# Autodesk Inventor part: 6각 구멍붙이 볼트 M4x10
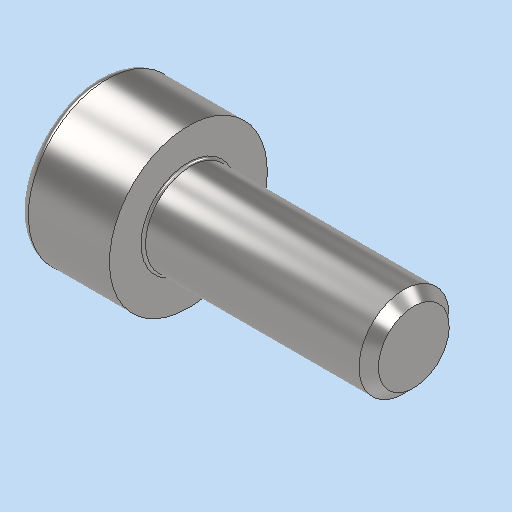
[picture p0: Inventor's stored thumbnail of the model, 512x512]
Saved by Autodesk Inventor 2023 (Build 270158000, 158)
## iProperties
Created: 2026-04
Part Number: 6각 구멍붙이 볼트 M4x10
Material: 강철, 연강
Description: 6각머리 태핑 나사
Document SubType Name: Modeling
Designer: home
Density: 7.85 g/cm^3
Appearance: 기본값
Author: jhkim
Sending System: Autodesk Inventor 2027
Preprocessor: ST-DEVELOPER v20.1
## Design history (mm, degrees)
feature "Solid1"
node "솔리드1"
